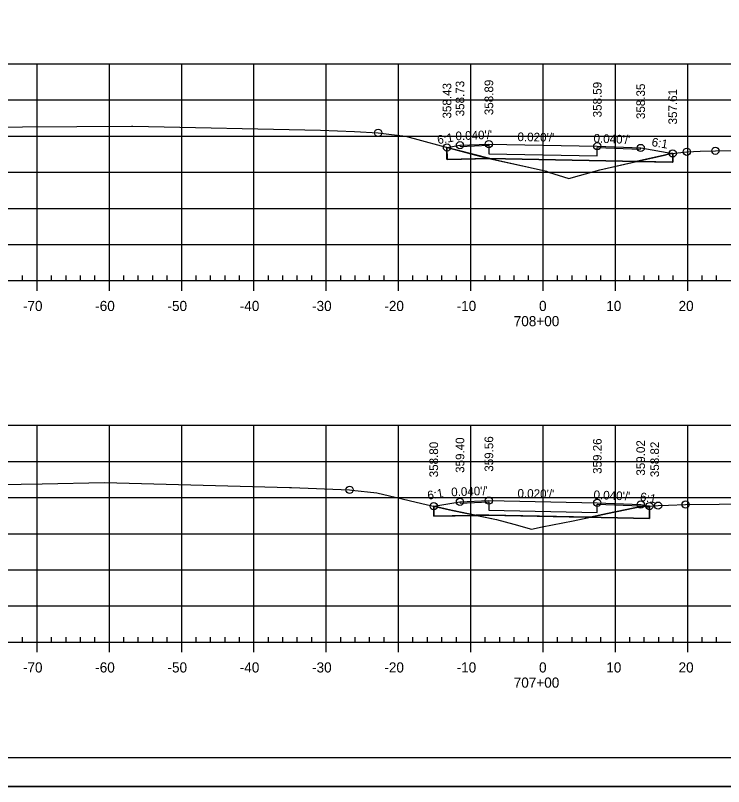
# Model space of a CAD drawing. Extents: x 1359801 to 1362404, y 372415 to 374228.
# Drawn here: x 1360514.5 to 1360612.5, y 372947.9 to 373054.6 of the extents above; entities that cross this region are included whole.
import ezdxf

# ---------------------------------------------------------------- set-up
doc = ezdxf.new("R2010")
doc.units = 0
for name, color, linetype in [('S_DRG_PT_SYM', 7, 'Continuous'), ('S_ELECTRIC_UTILITIES_ANNOT', 7, 'Continuous'), ('S_IRON_PIN', 7, 'Continuous'), ('S_MAILBOX', 7, 'Continuous'), ('S_PRIMARY_CTL', 7, 'Continuous'), ('S_SANITARY_SEWER', 7, 'Continuous'), ('S_SHOULDER', 7, 'Continuous'), ('S_UNDERGROUND_CABLE', 7, 'Continuous'), ('S_UTL_PT_SYM', 7, 'Continuous'), ('S_WATER_UTILITIES', 7, 'Continuous')]:
    doc.layers.add(name, color=color, linetype=linetype)

msp = doc.modelspace()

# ---------------------------------------------------------------- linework, layer by layer
at = {"layer": 'S_DRG_PT_SYM'}
for points in [[(1360507.9, 373039.13), (1360530.59, 373039.29), (1360530.64, 373039.3), (1360530.77, 373039.29), (1360556.73, 373038.75), (1360561.44, 373038.53), (1360564.72, 373038.37), (1360566.19, 373038.19), (1360568.5, 373037.89), (1360575.66, 373035.97), (1360579.59, 373034.93), (1360585.72, 373033.57), (1360587.98, 373033.06), (1360588.29, 373032.94), (1360591.08, 373032.04), (1360592.58, 373032.46), (1360595.4, 373033.25), (1360604.32, 373035.3), (1360605.14, 373035.5), (1360605.33, 373035.52), (1360607.42, 373035.75), (1360609.26, 373035.81), (1360611.36, 373035.89), (1360616.7, 373035.99)], [(1360503.74, 372989.57), (1360518.23, 372989.83), (1360526.87, 372989.99), (1360552.46, 372989.3), (1360552.7, 372989.3), (1360552.72, 372989.3), (1360560.76, 372988.98), (1360561.09, 372988.94), (1360564.53, 372988.56), (1360570.75, 372987.11), (1360574.16, 372986.31), (1360575, 372986.14), (1360581.1, 372984.87), (1360583.47, 372984.23), (1360585.93, 372983.55), (1360587.4, 372983.86), (1360591.69, 372984.72), (1360596.43, 372985.69), (1360601.32, 372986.71), (1360602.09, 372986.74), (1360603.44, 372986.8), (1360604.89, 372986.86), (1360607.25, 372986.95), (1360611.91, 372987.01), (1360617.8, 372987.09)]]:
    msp.add_lwpolyline(points, dxfattribs=at)
at = {"layer": 'S_ELECTRIC_UTILITIES_ANNOT'}
for p, q in [((1360575.66, 373035.97), (1360574.23, 373036.35)), ((1360574.23, 373036.35), (1360574.24, 373034.69)), ((1360580.14, 373034.81), (1360575.66, 373035.97)), ((1360574.24, 373034.69), (1360580.14, 373034.81)), ((1360605.46, 373034.3), (1360605.46, 373035.53)), ((1360600.42, 373034.4), (1360595.11, 373034.51)), ((1360600.42, 373034.4), (1360605.46, 373034.3)), ((1360572.4, 372986.72), (1360572.41, 372985.33)), ((1360602.25, 372985.04), (1360602.24, 372986.74)), ((1360578.31, 372985.45), (1360575, 372986.14)), ((1360572.41, 372985.33), (1360578.31, 372985.45)), ((1360594.07, 372985.2), (1360602.25, 372985.04)), ((1360594.07, 372985.2), (1360594.07, 372985.2))]:
    msp.add_line(p, q, dxfattribs=at)
for points in [[(1360595.11, 373034.51), (1360580.03, 373034.81), (1360580.16, 373034.81)], [(1360580.16, 373034.81), (1360580.16, 373034.81), (1360585.72, 373033.57), (1360587.98, 373033.06), (1360588.29, 373032.94), (1360591.08, 373032.04), (1360592.58, 373032.46), (1360595.4, 373033.25), (1360600.42, 373034.4)], [(1360605.46, 373035.53), (1360605.33, 373035.52), (1360605.14, 373035.5), (1360604.32, 373035.3), (1360600.42, 373034.4)], [(1360575, 372986.14), (1360574.16, 372986.31), (1360572.4, 372986.72)], [(1360602.24, 372986.74), (1360602.09, 372986.74), (1360601.32, 372986.71), (1360596.43, 372985.69), (1360594.07, 372985.2)], [(1360594.07, 372985.2), (1360580.03, 372985.49), (1360578.24, 372985.47)], [(1360578.24, 372985.47), (1360581.1, 372984.87), (1360583.47, 372984.23), (1360585.93, 372983.55), (1360587.4, 372983.86), (1360591.69, 372984.72), (1360594.07, 372985.2)]]:
    msp.add_lwpolyline(points, dxfattribs=at)
at = {"layer": 'S_MAILBOX'}
for p, q in [((1360442.53, 373047.92), (1360732.53, 373047.92)), ((1360517.53, 373017.92), (1360517.53, 373047.92)), ((1360527.53, 373017.92), (1360527.53, 373047.92)), ((1360537.53, 373017.92), (1360537.53, 373047.92)), ((1360547.53, 373017.92), (1360547.53, 373047.92)), ((1360557.53, 373017.92), (1360557.53, 373047.92)), ((1360567.53, 373017.92), (1360567.53, 373047.92)), ((1360577.53, 373017.92), (1360577.53, 373047.92)), ((1360587.53, 373017.92), (1360587.53, 373047.92)), ((1360597.53, 373017.92), (1360597.53, 373047.92)), ((1360607.53, 373017.92), (1360607.53, 373047.92)), ((1360442.53, 373042.92), (1360732.53, 373042.92)), ((1360442.53, 373037.92), (1360732.53, 373037.92)), ((1360442.53, 373032.92), (1360732.53, 373032.92)), ((1360442.53, 373027.92), (1360732.53, 373027.92)), ((1360442.53, 373022.92), (1360732.53, 373022.92)), ((1360442.53, 373017.92), (1360732.53, 373017.92)), ((1360442.53, 372997.92), (1360732.53, 372997.92)), ((1360517.53, 372967.92), (1360517.53, 372997.92)), ((1360527.53, 372967.92), (1360527.53, 372997.92)), ((1360537.53, 372967.92), (1360537.53, 372997.92)), ((1360547.53, 372967.92), (1360547.53, 372997.92)), ((1360557.53, 372967.92), (1360557.53, 372997.92)), ((1360567.53, 372967.92), (1360567.53, 372997.92)), ((1360577.53, 372967.92), (1360577.53, 372997.92)), ((1360587.53, 372967.92), (1360587.53, 372997.92)), ((1360597.53, 372967.92), (1360597.53, 372997.92)), ((1360607.53, 372967.92), (1360607.53, 372997.92)), ((1360442.53, 372992.92), (1360732.53, 372992.92)), ((1360442.53, 372987.92), (1360732.53, 372987.92)), ((1360442.53, 372982.92), (1360732.53, 372982.92)), ((1360442.53, 372977.92), (1360732.53, 372977.92)), ((1360442.53, 372972.92), (1360732.53, 372972.92)), ((1360442.53, 372967.92), (1360732.53, 372967.92))]:
    msp.add_line(p, q, dxfattribs=at)
at = {"layer": 'S_SANITARY_SEWER'}
for points in [[(1360574.23, 373036.35), (1360576.03, 373036.65), (1360580.03, 373036.81), (1360595.03, 373036.51), (1360595.03, 373036.51), (1360601.03, 373036.27), (1360605.46, 373035.53)], [(1360572.4, 372986.72), (1360576.03, 372987.33), (1360580.03, 372987.49), (1360595.03, 372987.19), (1360595.03, 372987.19), (1360601.03, 372986.95), (1360602.24, 372986.74)]]:
    msp.add_lwpolyline(points, dxfattribs=at)
at = {"layer": 'S_SHOULDER'}
for p, q in [((1360574.23, 373034.69), (1360574.23, 373036.18)), ((1360605.46, 373035.36), (1360605.46, 373034.3)), ((1360605.46, 373034.3), (1360605.44, 373034.3)), ((1360572.4, 372985.33), (1360572.4, 372986.55)), ((1360602.24, 372986.57), (1360602.26, 372985.04)), ((1360602.26, 372985.04), (1360602.25, 372985.04)), ((1360417.13, 372947.94), (1360750.46, 372947.94))]:
    msp.add_line(p, q, dxfattribs=at)
for points in [[(1360417.12, 373161.28), (1360750.46, 373161.28), (1360750.46, 372947.94), (1360417.12, 372947.94)], [(1360663.45, 373157.38), (1360663.45, 373147.5), (1360699.18, 373147.5), (1360699.18, 373144.58), (1360722.38, 373144.58), (1360722.38, 373120.25), (1360745.71, 373120.25), (1360745.71, 372951.92), (1360429.53, 372951.92), (1360429.53, 373157.38)]]:
    msp.add_lwpolyline(points, close=True, dxfattribs=at)
for points in [[(1360574.23, 373036.18), (1360574.23, 373036.35), (1360576.03, 373036.65), (1360576.05, 373036.48), (1360580.03, 373036.64)], [(1360580.03, 373036.64), (1360580.03, 373035.48), (1360595.03, 373035.18), (1360595.03, 373036.34)], [(1360595.03, 373036.34), (1360601.01, 373036.1), (1360601.03, 373036.27), (1360605.46, 373035.53), (1360605.46, 373035.36)], [(1360605.44, 373034.3), (1360580.03, 373034.81), (1360574.24, 373034.69)], [(1360572.4, 372986.55), (1360572.4, 372986.72), (1360576.03, 372987.33), (1360576.05, 372987.16), (1360580.03, 372987.32)], [(1360580.03, 372987.32), (1360580.03, 372986.15), (1360595.02, 372985.85), (1360595.03, 372987.02)], [(1360595.03, 372987.02), (1360601.01, 372986.78), (1360602.24, 372986.57)], [(1360602.25, 372985.04), (1360580.03, 372985.49), (1360572.41, 372985.33)]]:
    msp.add_lwpolyline(points, dxfattribs=at)
for centre in [(1360564.72, 373038.37), (1360574.23, 373036.35), (1360576.03, 373036.65), (1360580.03, 373036.81), (1360595.03, 373036.51), (1360601.03, 373036.27), (1360605.46, 373035.53), (1360607.42, 373035.75), (1360611.36, 373035.89), (1360560.76, 372988.98), (1360576.03, 372987.33), (1360580.03, 372987.49), (1360572.4, 372986.72), (1360595.03, 372987.19), (1360601.03, 372986.95), (1360602.24, 372986.74), (1360603.44, 372986.8), (1360607.25, 372986.95)]:
    msp.add_circle(centre, 0.5, dxfattribs=at)
at = {"layer": 'S_UNDERGROUND_CABLE'}
for p, q in [((1360574.23, 373036.35), (1360574.23, 373034.69)), ((1360605.46, 373035.53), (1360605.46, 373034.3)), ((1360572.4, 372986.72), (1360572.4, 372985.33)), ((1360602.24, 372986.74), (1360602.26, 372985.04))]:
    msp.add_line(p, q, dxfattribs=at)
for points in [[(1360574.24, 373034.69), (1360580.03, 373034.81), (1360605.44, 373034.3)], [(1360572.41, 372985.33), (1360580.03, 372985.49), (1360602.25, 372985.04)]]:
    msp.add_lwpolyline(points, dxfattribs=at)
at = {"layer": 'S_UTL_PT_SYM'}
msp.add_line((1360745.71, 372951.92), (1360429.53, 372951.92), dxfattribs=at)
at = {"layer": 'S_WATER_UTILITIES'}
for p, q in [((1360442.53, 373017.92), (1360732.53, 373017.92)), ((1360515.53, 373017.92), (1360515.53, 373018.62)), ((1360517.53, 373016.52), (1360517.53, 373017.92)), ((1360519.53, 373017.92), (1360519.53, 373018.62)), ((1360521.53, 373017.92), (1360521.53, 373018.62)), ((1360523.53, 373017.92), (1360523.53, 373018.62)), ((1360525.53, 373017.92), (1360525.53, 373018.62)), ((1360527.53, 373016.52), (1360527.53, 373017.92)), ((1360529.53, 373017.92), (1360529.53, 373018.62)), ((1360531.53, 373017.92), (1360531.53, 373018.62)), ((1360533.53, 373017.92), (1360533.53, 373018.62)), ((1360535.53, 373017.92), (1360535.53, 373018.62)), ((1360537.53, 373016.52), (1360537.53, 373017.92)), ((1360539.53, 373017.92), (1360539.53, 373018.62)), ((1360541.53, 373017.92), (1360541.53, 373018.62)), ((1360543.53, 373017.92), (1360543.53, 373018.62)), ((1360545.53, 373017.92), (1360545.53, 373018.62)), ((1360547.53, 373016.52), (1360547.53, 373017.92)), ((1360549.53, 373017.92), (1360549.53, 373018.62)), ((1360551.53, 373017.92), (1360551.53, 373018.62)), ((1360553.53, 373017.92), (1360553.53, 373018.62)), ((1360555.53, 373017.92), (1360555.53, 373018.62)), ((1360557.53, 373016.52), (1360557.53, 373017.92)), ((1360559.53, 373017.92), (1360559.53, 373018.62)), ((1360561.53, 373017.92), (1360561.53, 373018.62)), ((1360563.53, 373017.92), (1360563.53, 373018.62)), ((1360565.53, 373017.92), (1360565.53, 373018.62)), ((1360567.53, 373016.52), (1360567.53, 373017.92)), ((1360569.53, 373017.92), (1360569.53, 373018.62)), ((1360571.53, 373017.92), (1360571.53, 373018.62)), ((1360573.53, 373017.92), (1360573.53, 373018.62)), ((1360575.53, 373017.92), (1360575.53, 373018.62)), ((1360577.53, 373016.52), (1360577.53, 373017.92)), ((1360579.53, 373017.92), (1360579.53, 373018.62)), ((1360581.53, 373017.92), (1360581.53, 373018.62)), ((1360583.53, 373017.92), (1360583.53, 373018.62)), ((1360585.53, 373017.92), (1360585.53, 373018.62)), ((1360587.53, 373016.52), (1360587.53, 373017.92)), ((1360589.53, 373017.92), (1360589.53, 373018.62)), ((1360591.53, 373017.92), (1360591.53, 373018.62)), ((1360593.53, 373017.92), (1360593.53, 373018.62)), ((1360595.53, 373017.92), (1360595.53, 373018.62)), ((1360597.53, 373016.52), (1360597.53, 373017.92)), ((1360599.53, 373017.92), (1360599.53, 373018.62)), ((1360601.53, 373017.92), (1360601.53, 373018.62)), ((1360603.53, 373017.92), (1360603.53, 373018.62)), ((1360605.53, 373017.92), (1360605.53, 373018.62)), ((1360607.53, 373016.52), (1360607.53, 373017.92)), ((1360609.53, 373017.92), (1360609.53, 373018.62)), ((1360611.53, 373017.92), (1360611.53, 373018.62)), ((1360515.53, 372967.92), (1360515.53, 372968.62)), ((1360519.53, 372967.92), (1360519.53, 372968.62)), ((1360521.53, 372967.92), (1360521.53, 372968.62)), ((1360523.53, 372967.92), (1360523.53, 372968.62)), ((1360525.53, 372967.92), (1360525.53, 372968.62)), ((1360529.53, 372967.92), (1360529.53, 372968.62)), ((1360531.53, 372967.92), (1360531.53, 372968.62)), ((1360533.53, 372967.92), (1360533.53, 372968.62)), ((1360535.53, 372967.92), (1360535.53, 372968.62)), ((1360539.53, 372967.92), (1360539.53, 372968.62)), ((1360541.53, 372967.92), (1360541.53, 372968.62)), ((1360543.53, 372967.92), (1360543.53, 372968.62)), ((1360545.53, 372967.92), (1360545.53, 372968.62)), ((1360549.53, 372967.92), (1360549.53, 372968.62)), ((1360551.53, 372967.92), (1360551.53, 372968.62)), ((1360553.53, 372967.92), (1360553.53, 372968.62)), ((1360555.53, 372967.92), (1360555.53, 372968.62)), ((1360559.53, 372967.92), (1360559.53, 372968.62)), ((1360561.53, 372967.92), (1360561.53, 372968.62)), ((1360563.53, 372967.92), (1360563.53, 372968.62)), ((1360565.53, 372967.92), (1360565.53, 372968.62)), ((1360569.53, 372967.92), (1360569.53, 372968.62)), ((1360571.53, 372967.92), (1360571.53, 372968.62)), ((1360573.53, 372967.92), (1360573.53, 372968.62)), ((1360575.53, 372967.92), (1360575.53, 372968.62)), ((1360579.53, 372967.92), (1360579.53, 372968.62)), ((1360581.53, 372967.92), (1360581.53, 372968.62)), ((1360583.53, 372967.92), (1360583.53, 372968.62)), ((1360585.53, 372967.92), (1360585.53, 372968.62)), ((1360589.53, 372967.92), (1360589.53, 372968.62)), ((1360591.53, 372967.92), (1360591.53, 372968.62)), ((1360593.53, 372967.92), (1360593.53, 372968.62)), ((1360595.53, 372967.92), (1360595.53, 372968.62)), ((1360599.53, 372967.92), (1360599.53, 372968.62)), ((1360601.53, 372967.92), (1360601.53, 372968.62)), ((1360603.53, 372967.92), (1360603.53, 372968.62)), ((1360605.53, 372967.92), (1360605.53, 372968.62)), ((1360609.53, 372967.92), (1360609.53, 372968.62)), ((1360611.53, 372967.92), (1360611.53, 372968.62)), ((1360442.53, 372967.92), (1360732.53, 372967.92)), ((1360517.53, 372966.52), (1360517.53, 372967.92)), ((1360527.53, 372966.52), (1360527.53, 372967.92)), ((1360537.53, 372966.52), (1360537.53, 372967.92)), ((1360547.53, 372966.52), (1360547.53, 372967.92)), ((1360557.53, 372966.52), (1360557.53, 372967.92)), ((1360567.53, 372966.52), (1360567.53, 372967.92)), ((1360577.53, 372966.52), (1360577.53, 372967.92)), ((1360587.53, 372966.52), (1360587.53, 372967.92)), ((1360597.53, 372966.52), (1360597.53, 372967.92)), ((1360607.53, 372966.52), (1360607.53, 372967.92))]:
    msp.add_line(p, q, dxfattribs=at)

# ---------------------------------------------------------------- texts
at = {"layer": 'S_IRON_PIN'}
for s, rotation, p in [('358.73', 90, (1360576.63, 373040.65)), ('358.89', 90, (1360580.63, 373040.81)), ('358.59', 90, (1360595.63, 373040.51)), ('358.43', 90, (1360574.83, 373040.35)), ('358.35', 90, (1360601.63, 373040.27)), ('357.61', 90, (1360606.06, 373039.53)), ('6:1', 9.4623, (1360572.99, 373036.8)), ("0.040'/'", 2.2906, (1360575.43, 373037.33)), ("0.020'/'", 358.8542, (1360583.98, 373037.23)), ("0.040'/'", 357.7094, (1360594.49, 373037.03)), ('6:1', 350.5377, (1360602.48, 373036.54)), ('359.56', 90, (1360580.63, 372991.49)), ('358.80', 90, (1360573, 372990.72)), ('359.40', 90, (1360576.63, 372991.33)), ('359.26', 90, (1360595.63, 372991.19)), ('359.02', 90, (1360601.63, 372990.95)), ('358.82', 90, (1360603.57, 372990.74)), ('6:1', 9.4623, (1360571.62, 372987.61)), ("0.040'/'", 2.2906, (1360574.84, 372988.08)), ("0.020'/'", 358.8542, (1360583.98, 372987.91)), ("0.040'/'", 357.7094, (1360594.49, 372987.71)), ('6:1', 350.5377, (1360600.87, 372987.48))]:
    msp.add_text(s, height=1.2, rotation=rotation, dxfattribs=at).set_placement(p)
at = {"layer": 'S_PRIMARY_CTL'}
for s, p in [('-70', (1360515.57, 373013.72)), ('-60', (1360525.57, 373013.72)), ('-50', (1360535.57, 373013.72)), ('-40', (1360545.57, 373013.72)), ('-30', (1360555.57, 373013.72)), ('-20', (1360565.57, 373013.72)), ('-10', (1360575.57, 373013.72)), ('0', (1360586.97, 373013.72)), ('10', (1360596.27, 373013.72)), ('20', (1360606.27, 373013.72)), ('708+00', (1360583.47, 373011.62)), ('-70', (1360515.57, 372963.72)), ('-60', (1360525.57, 372963.72)), ('-50', (1360535.57, 372963.72)), ('-40', (1360545.57, 372963.72)), ('-30', (1360555.57, 372963.72)), ('-20', (1360565.57, 372963.72)), ('-10', (1360575.57, 372963.72)), ('0', (1360586.97, 372963.72)), ('10', (1360596.27, 372963.72)), ('20', (1360606.27, 372963.72)), ('707+00', (1360583.47, 372961.62))]:
    msp.add_text(s, height=1.4, dxfattribs=at).set_placement(p)
at = {"layer": 'S_SHOULDER'}
for p in [(1360556.69, 373038.7), (1360552.65, 372989.25)]:
    msp.add_text('+', height=0.1, dxfattribs=at).set_placement(p)

doc.saveas('drawing.dxf')
